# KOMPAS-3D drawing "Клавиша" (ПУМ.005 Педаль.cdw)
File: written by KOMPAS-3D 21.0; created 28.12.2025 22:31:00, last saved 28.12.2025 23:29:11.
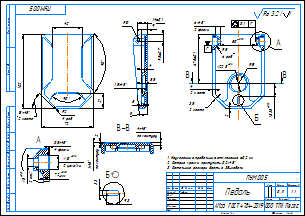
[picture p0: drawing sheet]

Sheet 1: A4x2, landscape

Document properties: Полное имя файла: ..\ПУМ.005 Педаль.m3d; Автор: User; Знак неуказанной шероховатости: 4; Параметр неуказанной шероховатости: Ra 3.2; Масса: 0.114089; Форматы листов документа: A4@4~2

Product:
- Part/product: Клавиша
    Материал: АМг6  ГОСТ 4784-2019 (density 2650 kg/m3)
    Масса: 0.114089
    Форматы листов документа: A4@4~2

Title block, sheet 1: Наименование: Педаль; designation: ПУМ.005; Материал: АМг6  ГОСТ 4784-2019; Масса: 0,11; Количество листов документа: 1; organisation: ООО ТПК Пегас; Форматы листов документа: A4 2; stored path: C:\Users\Гузель\Desktop\ПУМ\Чертежи\ПУМ.005 Педаль.cdw; Разработал: Гайсин

Views: Вид 1, Сверху, Проекционный вид 2, Местный разрез 1, Проекционный вид 3, Выносной элемент 4, Разрез В-В, Выносной элемент 6, Выносной элемент А, Выносной элемент, Выносной элемент Б
Referenced files in C:\Users\Гузель\Desktop\ПУМ\: ПУМ.005 Клавиша.m3d, ПУМ.005 Педаль.m3d
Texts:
  Клавиша
  по контуру
  Ra 3.2
  Ra 3.2 ( )
Dimensions and other numbers on the sheet: 72; 102; 21; 42; 2 места; 2; 4 рад; 10; 9; 5,5; 1,5; 4; 5; 9,5±0,1; 14±0,1; 3,5; 6; 2 фаски; 67,5±0,1; 6 рад; 15; 18,35; 0,1; 22,5; 50; 2 цековки; 2 отв; 7,2; 0,5; 4 фаски; 1; 9,3; 3,3; 1:1; 0,11

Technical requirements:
  Неуказанные предельные отклонения  0,2 мм
  Острые кромки притупить 0,2х45
  Остальные размеры брать с 3д-модели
